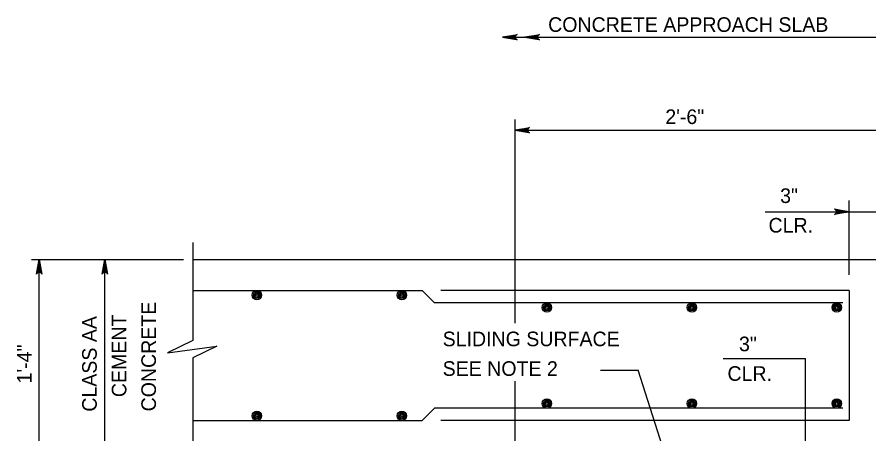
# Model space of a CAD drawing. Extents: x 636530 to 644067, y 294168 to 299122.
# Drawn here: x 639438 to 639612.8, y 297427.8 to 297513.4 of the extents above; entities that cross this region are included whole.
import ezdxf

# ---------------------------------------------------------------- set-up
doc = ezdxf.new("R2010")
doc.units = 0
doc.layers.add('1', color=7, linetype='Continuous')

msp = doc.modelspace()

# ---------------------------------------------------------------- linework, layer by layer
at = {"layer": '1'}
for p, q in [((639537.6, 297509.24), (639616.36, 297509.24)), ((639540.16, 297450.51), (639540.16, 297492.36)), ((639540.16, 297490.14), (639723.04, 297490.14)), ((639608.74, 297460.46), (639608.74, 297475.71)), ((639591.52, 297473.42), (639622.02, 297473.42)), ((639474.01, 297467.1), (639474.01, 297446.98)), ((639440.93, 297463.6), (639472.12, 297463.6)), ((639442.5, 297392.49), (639442.5, 297463.6)), ((639456, 297422.97), (639456, 297463.6)), ((639474.01, 297463.6), (639616.36, 297463.6)), ((639474.01, 297457.25), (639521.11, 297457.25)), ((639523.65, 297454.72), (639521.11, 297457.25)), ((639608.74, 297457.25), (639524.92, 297457.25)), ((639608.74, 297457.25), (639608.74, 297430.59)), ((639607.47, 297454.72), (639523.65, 297454.72)), ((639474.01, 297443.46), (639474.01, 297398.05)), ((639582.88, 297443.32), (639599.8, 297443.32)), ((639599.8, 297408.93), (639599.8, 297443.32)), ((639557.71, 297440.87), (639565.43, 297440.87)), ((639571.16, 297422.97), (639565.43, 297440.87)), ((639540.16, 297425.94), (639540.16, 297438.66)), ((639523.65, 297433.13), (639521.11, 297430.59)), ((639607.47, 297433.13), (639523.65, 297433.13)), ((639474.01, 297430.59), (639521.11, 297430.59)), ((639608.74, 297430.59), (639524.92, 297430.59))]:
    msp.add_line(p, q, dxfattribs=at)
for points in [[(639537.6, 297509.24), (639540.58, 297509.8), (639540.47, 297509.72), (639540.35, 297509.64), (639540.3, 297509.54), (639540.24, 297509.44), (639540.22, 297509.34), (639540.2, 297509.24), (639540.22, 297509.14), (639540.24, 297509.04), (639540.3, 297508.94), (639540.35, 297508.84), (639540.47, 297508.76), (639540.58, 297508.68), (639537.6, 297509.24), (639540.47, 297508.76), (639540.35, 297508.84), (639537.6, 297509.24), (639540.3, 297508.94), (639540.24, 297509.04), (639537.6, 297509.24), (639540.22, 297509.14), (639540.2, 297509.24), (639537.6, 297509.24), (639540.22, 297509.34), (639540.24, 297509.44), (639537.6, 297509.24), (639540.3, 297509.54), (639540.35, 297509.64), (639537.6, 297509.24), (639540.47, 297509.72)], [(639542.17, 297509.24), (639545.16, 297509.8), (639545.04, 297509.72), (639544.93, 297509.64), (639544.87, 297509.54), (639544.81, 297509.44), (639544.79, 297509.34), (639544.77, 297509.24), (639544.79, 297509.14), (639544.81, 297509.04), (639544.87, 297508.94), (639544.93, 297508.84), (639545.04, 297508.76), (639545.16, 297508.68), (639542.17, 297509.24), (639545.04, 297508.76), (639544.93, 297508.84), (639542.17, 297509.24), (639544.87, 297508.94), (639544.81, 297509.04), (639542.17, 297509.24), (639544.79, 297509.14), (639544.77, 297509.24), (639542.17, 297509.24), (639544.79, 297509.34), (639544.81, 297509.44), (639542.17, 297509.24), (639544.87, 297509.54), (639544.93, 297509.64), (639542.17, 297509.24), (639545.04, 297509.72)], [(639540.16, 297490.14), (639543.14, 297490.7), (639543.02, 297490.62), (639542.91, 297490.54), (639542.85, 297490.44), (639542.79, 297490.34), (639542.77, 297490.24), (639542.76, 297490.14), (639542.77, 297490.04), (639542.79, 297489.94), (639542.85, 297489.84), (639542.91, 297489.74), (639543.02, 297489.66), (639543.14, 297489.58), (639540.16, 297490.14), (639543.02, 297489.66), (639542.91, 297489.74), (639540.16, 297490.14), (639542.85, 297489.84), (639542.79, 297489.94), (639540.16, 297490.14), (639542.77, 297490.04), (639542.76, 297490.14), (639540.16, 297490.14), (639542.77, 297490.24), (639542.79, 297490.34), (639540.16, 297490.14), (639542.85, 297490.44), (639542.91, 297490.54), (639540.16, 297490.14), (639543.02, 297490.62)], [(639608.74, 297473.42), (639605.75, 297472.86), (639605.87, 297472.94), (639605.98, 297473.02), (639606.04, 297473.12), (639606.1, 297473.22), (639606.12, 297473.32), (639606.14, 297473.42), (639606.12, 297473.52), (639606.1, 297473.62), (639606.04, 297473.72), (639605.98, 297473.82), (639605.87, 297473.9), (639605.75, 297473.98), (639608.74, 297473.42), (639605.87, 297473.9), (639605.98, 297473.82), (639608.74, 297473.42), (639606.04, 297473.72), (639606.1, 297473.62), (639608.74, 297473.42), (639606.12, 297473.52), (639606.14, 297473.42), (639608.74, 297473.42), (639606.12, 297473.32), (639606.1, 297473.22), (639608.74, 297473.42), (639606.04, 297473.12), (639605.98, 297473.02), (639608.74, 297473.42), (639605.87, 297472.94)], [(639442.5, 297463.6), (639443.06, 297460.62), (639442.9, 297460.85), (639442.7, 297460.97), (639442.5, 297461), (639442.3, 297460.97), (639442.1, 297460.85), (639441.94, 297460.62), (639442.5, 297463.6), (639442.1, 297460.85), (639442.3, 297460.97), (639442.5, 297463.6), (639442.5, 297461), (639442.7, 297460.97), (639442.5, 297463.6), (639442.9, 297460.85)], [(639456, 297463.6), (639456.55, 297460.62), (639456.48, 297460.74), (639456.4, 297460.85), (639456.3, 297460.91), (639456.2, 297460.97), (639456.1, 297460.99), (639456, 297461), (639455.9, 297460.99), (639455.8, 297460.97), (639455.7, 297460.91), (639455.6, 297460.85), (639455.52, 297460.74), (639455.44, 297460.62), (639456, 297463.6), (639455.52, 297460.74), (639455.6, 297460.85), (639456, 297463.6), (639455.7, 297460.91), (639455.8, 297460.97), (639456, 297463.6), (639455.9, 297460.99), (639456, 297461), (639456, 297463.6), (639456.1, 297460.99), (639456.2, 297460.97), (639456, 297463.6), (639456.3, 297460.91), (639456.4, 297460.85), (639456, 297463.6), (639456.48, 297460.74)], [(639474.01, 297446.98), (639468.83, 297444.44), (639478.98, 297445.82), (639474.01, 297443.46)]]:
    msp.add_lwpolyline(points, dxfattribs=at)
for centre, radius in [((639487.18, 297456.3), 0.952), ((639487.18, 297456.3), 0.714), ((639516.94, 297456.3), 0.952), ((639516.94, 297456.3), 0.714), ((639487.18, 297456.3), 0.476), ((639487.18, 297456.3), 0.238), ((639516.94, 297456.3), 0.476), ((639516.94, 297456.3), 0.238), ((639546.7, 297453.77), 0.952), ((639546.7, 297453.77), 0.714), ((639546.7, 297453.77), 0.476), ((639546.7, 297453.77), 0.238), ((639576.47, 297453.77), 0.952), ((639576.47, 297453.77), 0.714), ((639576.47, 297453.77), 0.476), ((639576.47, 297453.77), 0.238), ((639606.2, 297453.77), 0.952), ((639606.2, 297453.77), 0.714), ((639606.2, 297453.77), 0.476), ((639606.2, 297453.77), 0.238), ((639546.7, 297434.08), 0.952), ((639546.7, 297434.08), 0.714), ((639546.7, 297434.08), 0.476), ((639546.7, 297434.08), 0.238), ((639576.47, 297434.08), 0.952), ((639576.47, 297434.08), 0.714), ((639576.47, 297434.08), 0.476), ((639576.47, 297434.08), 0.238), ((639606.2, 297434.08), 0.952), ((639606.2, 297434.08), 0.714), ((639606.2, 297434.08), 0.476), ((639606.2, 297434.08), 0.238), ((639487.18, 297431.54), 0.952), ((639516.94, 297431.54), 0.952), ((639487.18, 297431.54), 0.714), ((639487.18, 297431.54), 0.476), ((639487.18, 297431.54), 0.238), ((639516.94, 297431.54), 0.714), ((639516.94, 297431.54), 0.476), ((639516.94, 297431.54), 0.238)]:
    msp.add_circle(centre, radius, dxfattribs=at)

# ---------------------------------------------------------------- texts
for s, p in [('CONCRETE APPROACH SLAB', (639546.96, 297510.31)), ('2\'-6"', (639571, 297491.4)), ('SLIDING SURFACE', (639525.31, 297445.81)), ('3"', (639586.13, 297444.78)), ('SEE NOTE 2', (639525.31, 297439.73)), ('CLR.', (639583.76, 297438.71))]:
    msp.add_text(s, height=3, dxfattribs=at).set_placement(p)
for s, rotation, p in [('3"', 360, (639594.57, 297475.2)), ('CLR.', 360, (639592.19, 297469.13)), ('CONCRETE', 90, (639466.47, 297432.44)), ('CLASS AA', 90, (639454.32, 297432.38)), ('CEMENT', 90, (639460.4, 297435.36)), ('1\'-4"', 90, (639440.96, 297438.18))]:
    msp.add_text(s, height=3, rotation=rotation, dxfattribs=at).set_placement(p)

doc.saveas('drawing.dxf')
